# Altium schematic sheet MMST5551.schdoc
size 127 x 101 mm
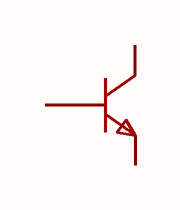
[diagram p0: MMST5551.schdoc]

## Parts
Q?  mmst5551(range:100-300)  [SOT-323-3_L2.0-W1.3-P1.30-LS2.1-BR]  (value not drawn)

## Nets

Not connected (* = marked no-connect by the designer): Q? 1(B) 2(E) 3(C)

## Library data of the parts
Q? = mmst5551(range:100-300): 晶体管类型:NPN;集电极电流(Ic):600mA;集射极击穿电压(Vceo):160V;耗散功率(Pd):200mW;直流电流增益(hFE):100;; Manufacturer: CJ(江苏长电/长晶); AddInBom: yes; ModelId: 59529c0d6fc749f28f2d0659e12986b4; ModelName: SOT-323-3_L2.0-W1.3-H1.0-LS2.1-P1.30; ModelTransform: 78.74,82.677,0,90,0,0,0.0005,0,0; type: NPN; Current - Collector(Ic): 600mA; Collector - Emitter Voltage VCEO: 160V; Pd - Power Dissipation: 200mW; DC Current Gain: 100; Transition frequency(fT): 300MHz; Current - Collector Cutoff: 50nA; Vce Saturation(VCE(sat)): 200mV; Emitter-Base Voltage(Vebo): 6V; Number: 1个NPN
